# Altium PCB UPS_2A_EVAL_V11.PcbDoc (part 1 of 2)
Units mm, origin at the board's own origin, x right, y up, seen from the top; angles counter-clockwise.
Board outline 85 x 55 mm, 4 copper layers (Top Layer, Mid1, Mid2, Bottom Layer), stack 1.572 mm thick; 131 components, 65 nets, 459 pads, 411 vias.
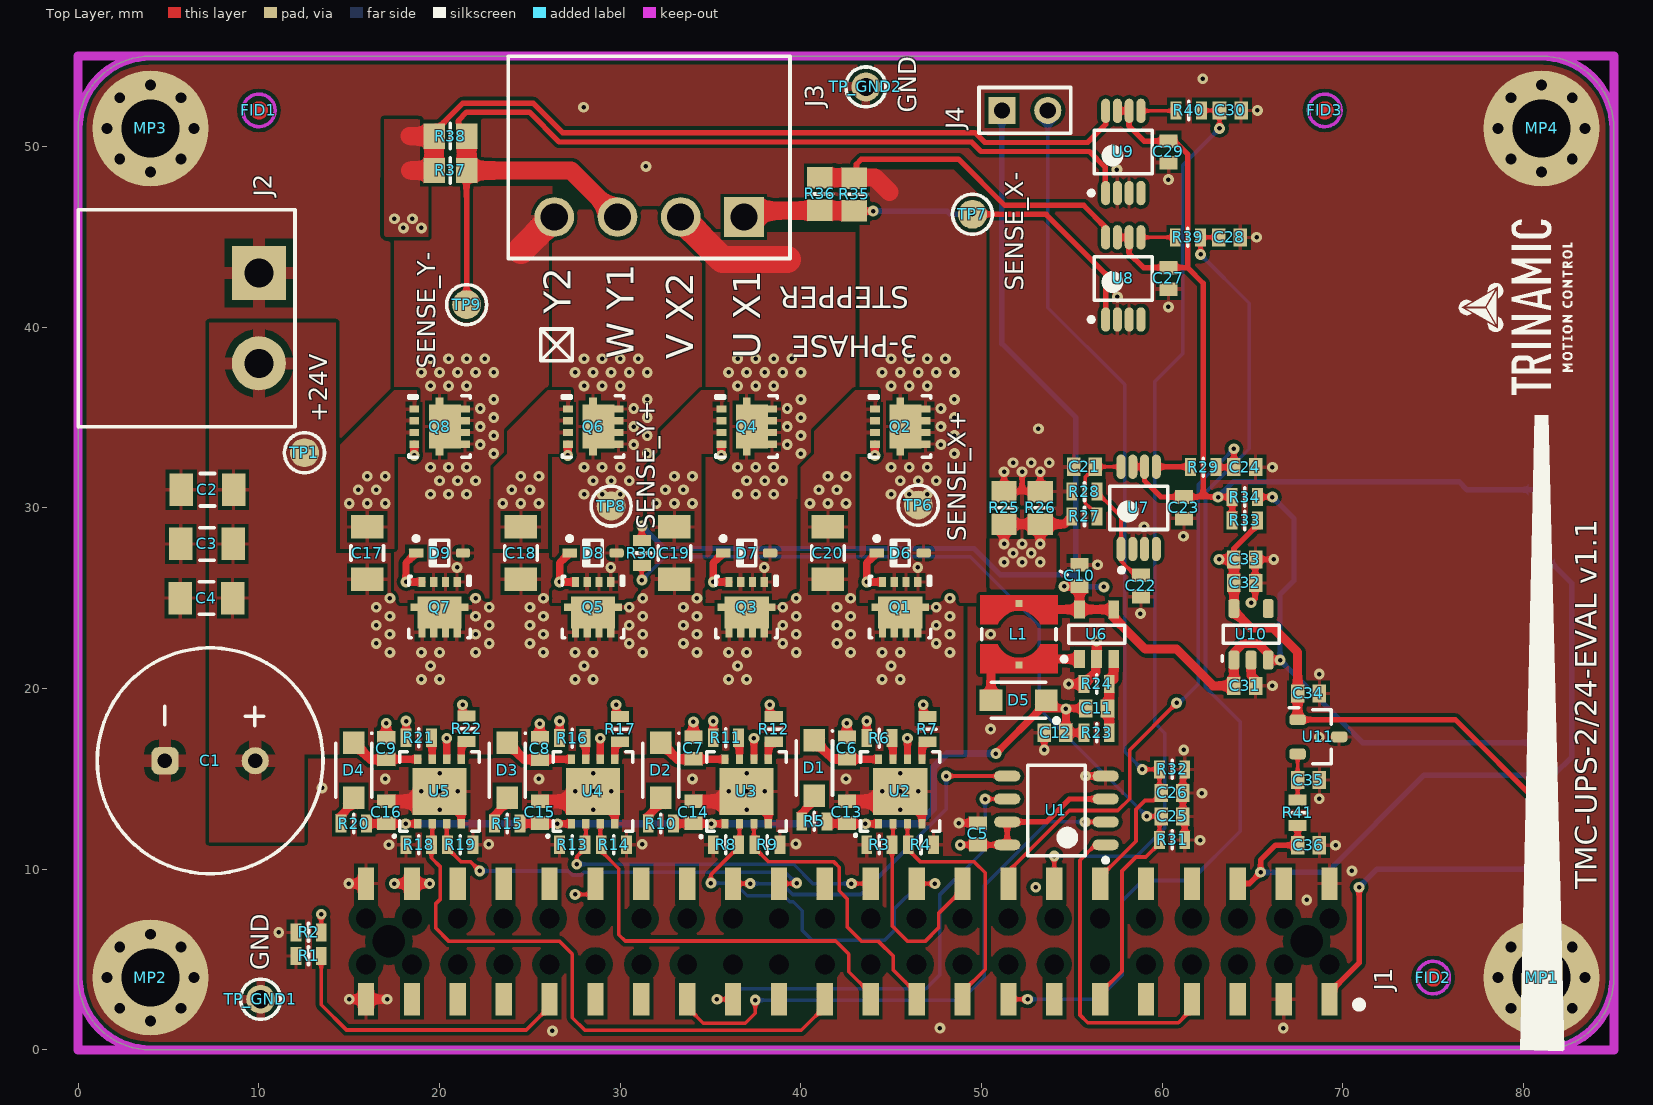
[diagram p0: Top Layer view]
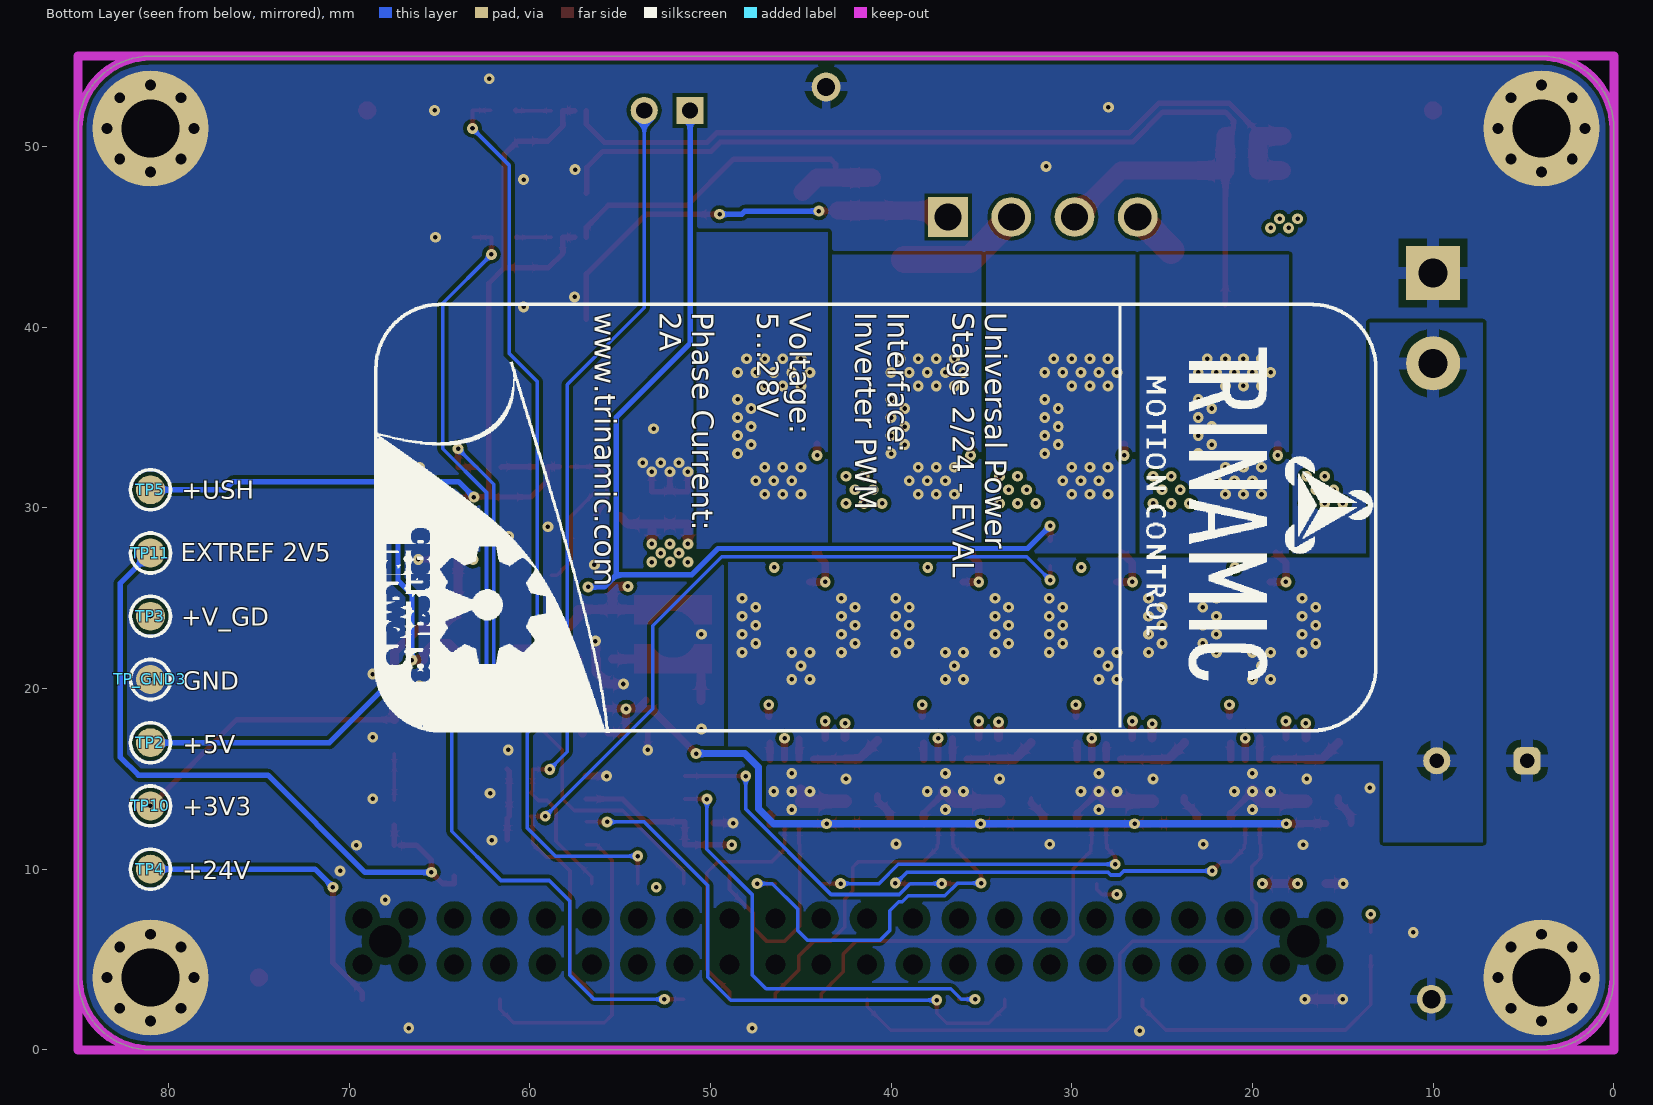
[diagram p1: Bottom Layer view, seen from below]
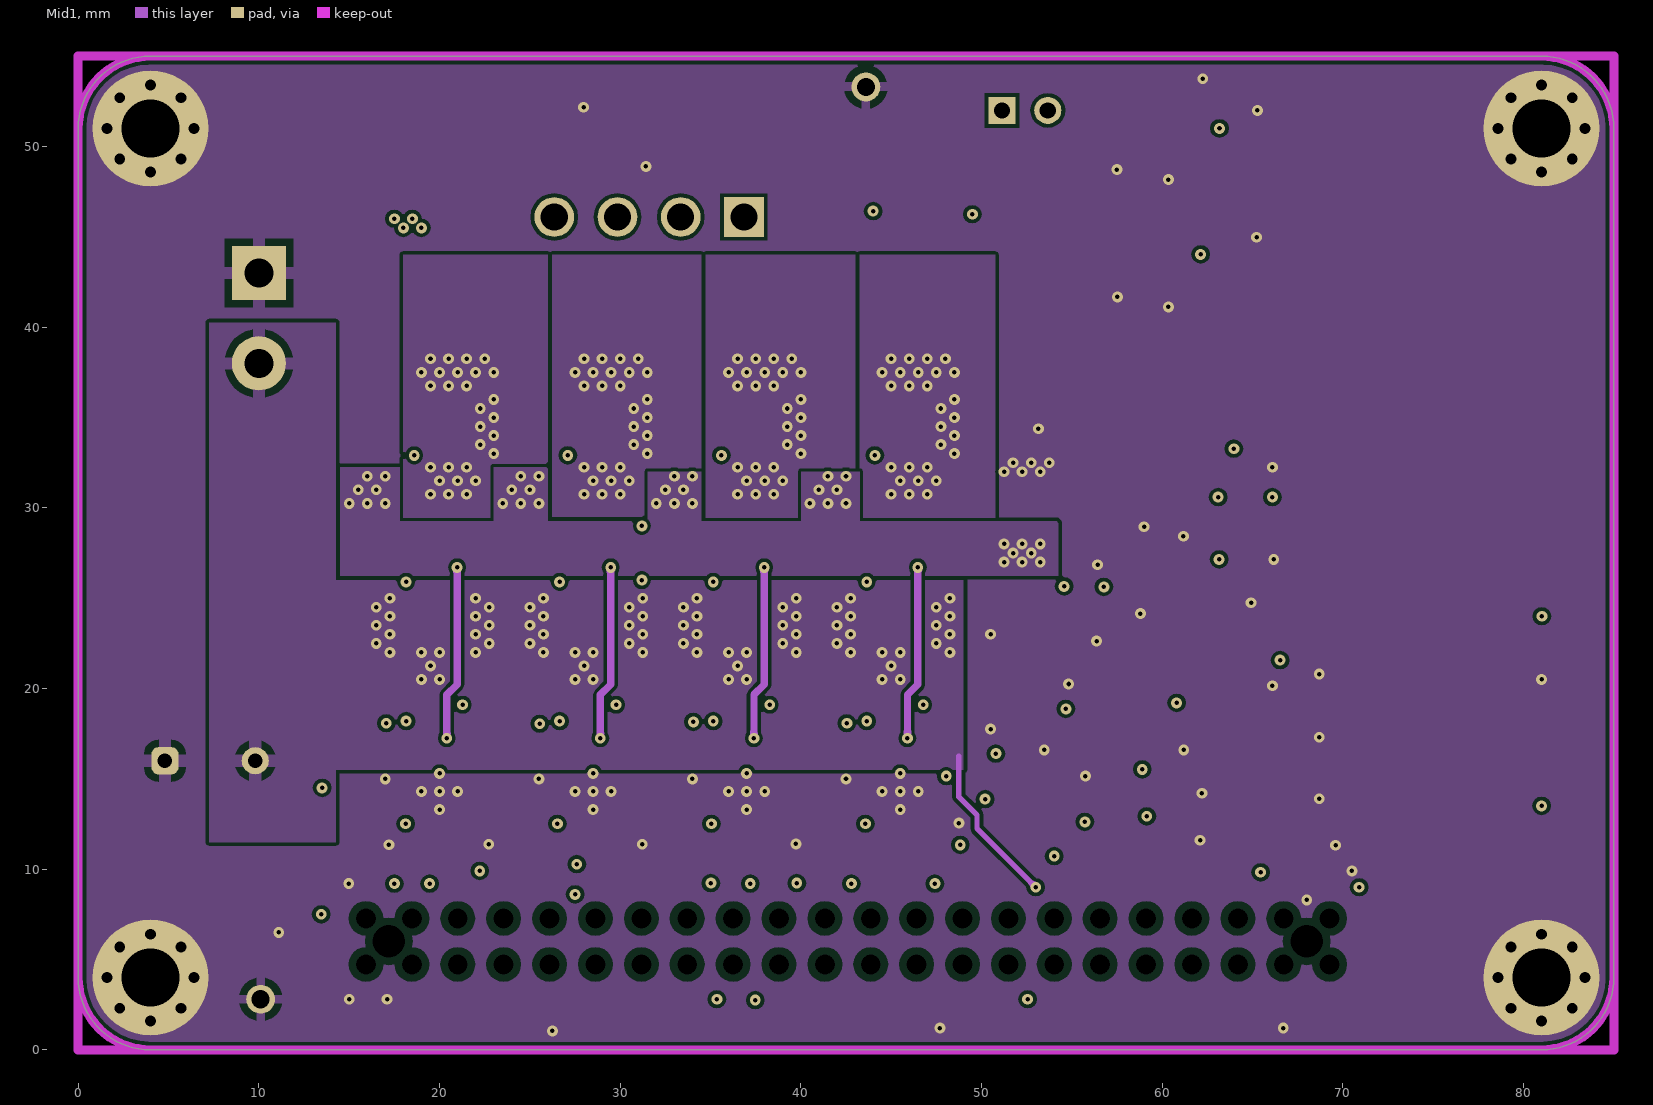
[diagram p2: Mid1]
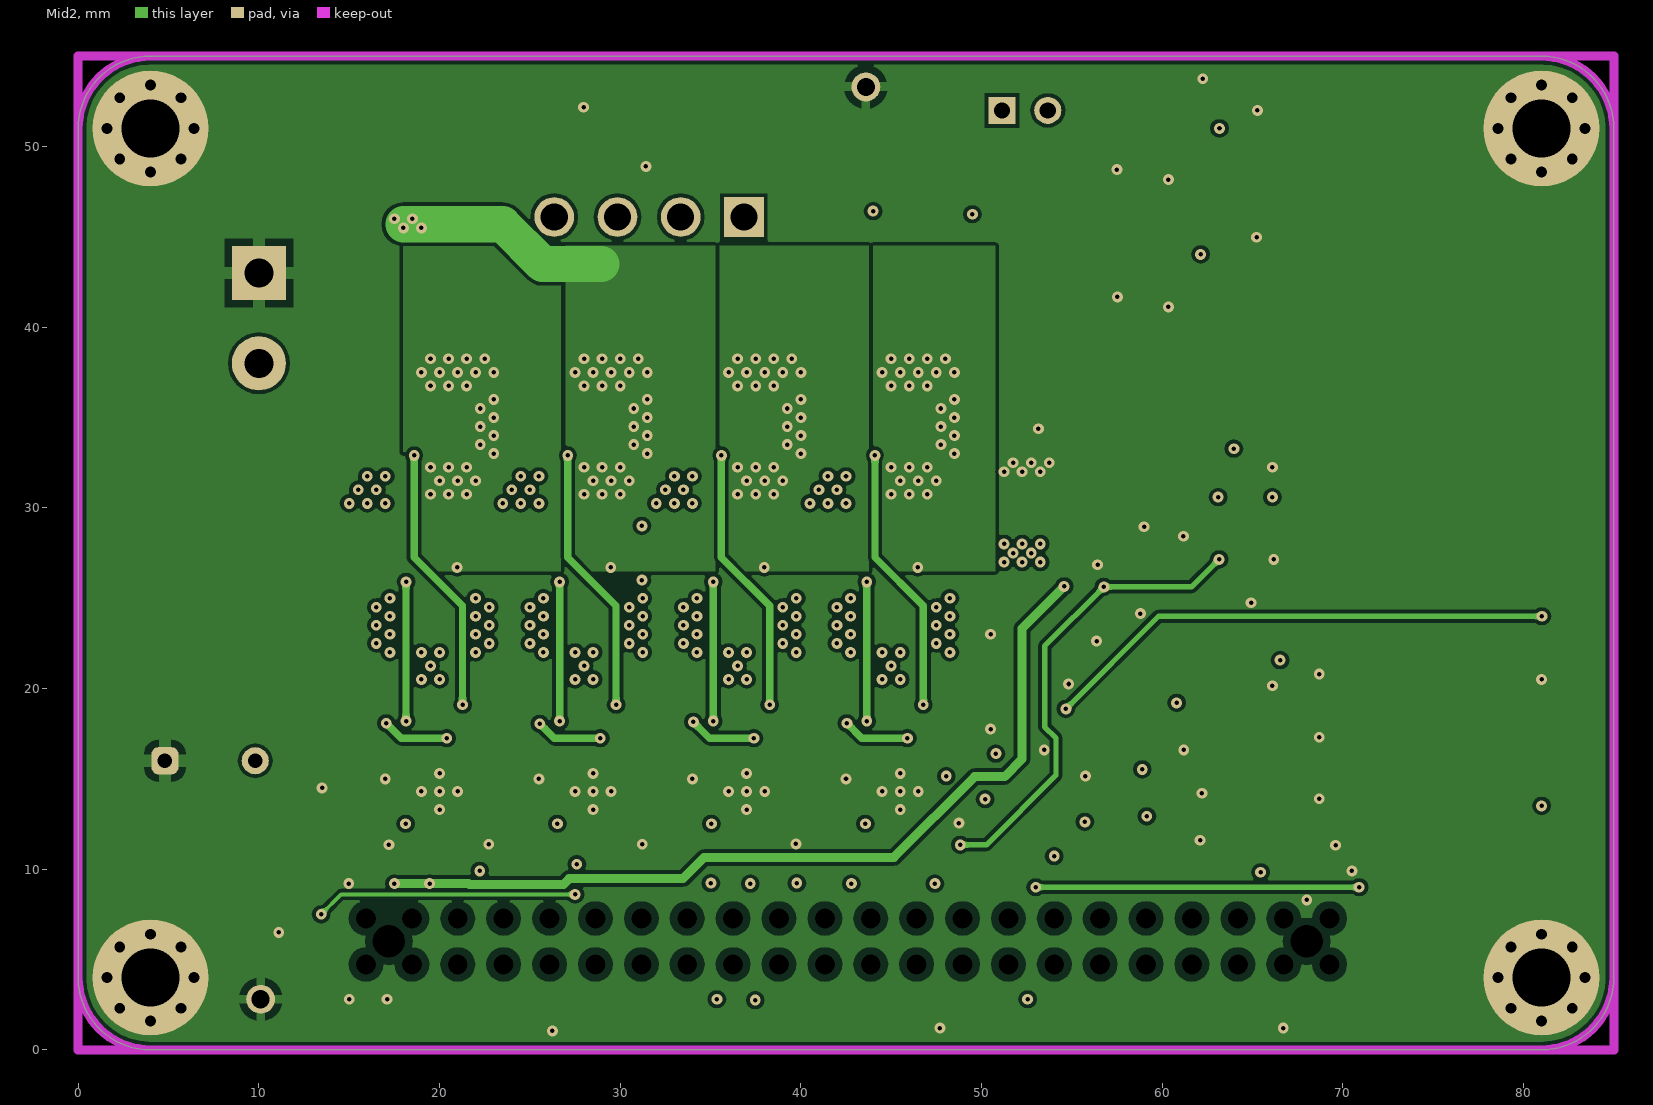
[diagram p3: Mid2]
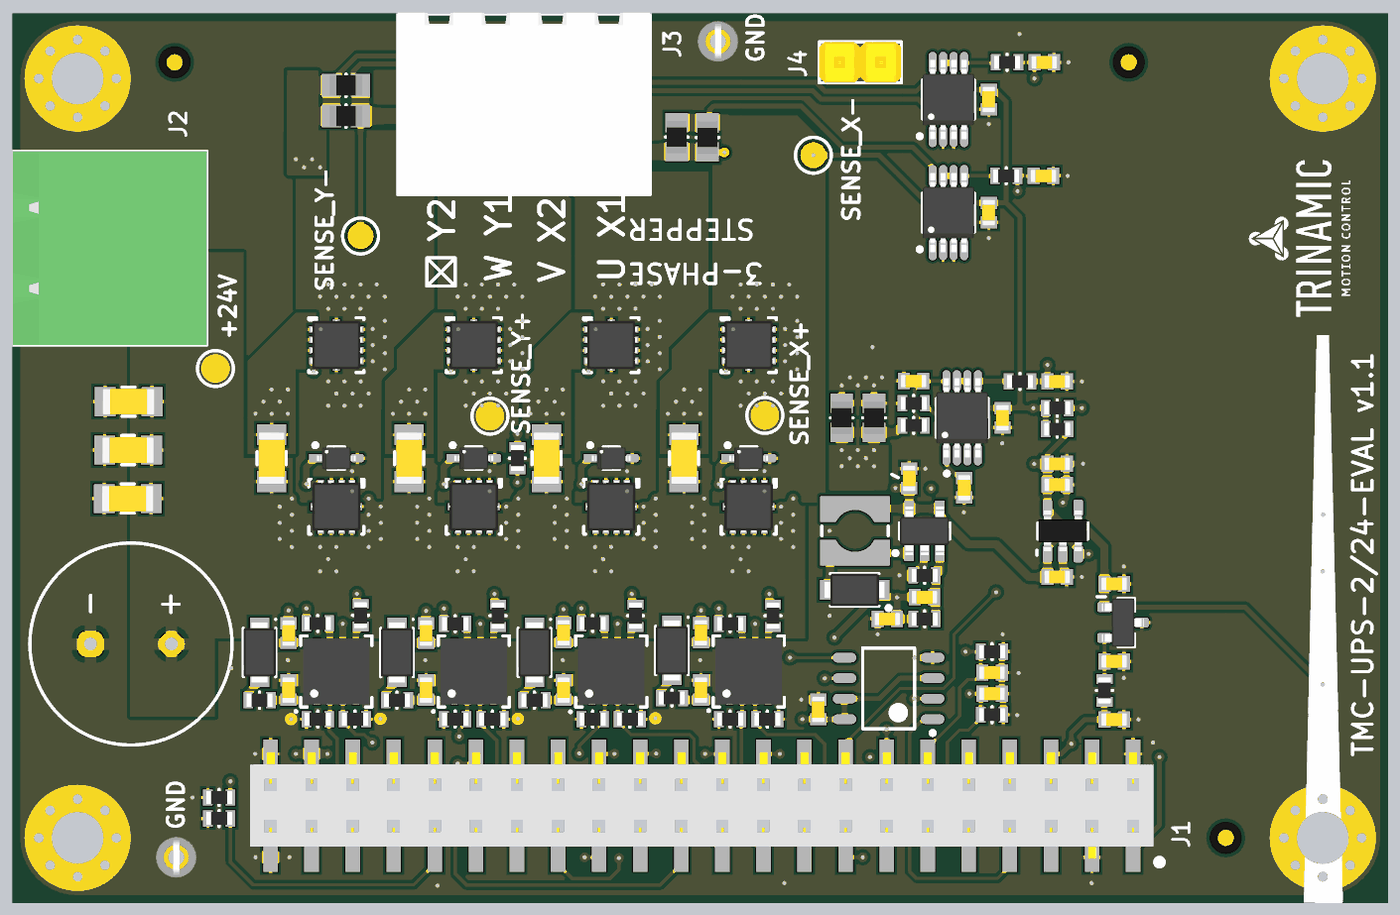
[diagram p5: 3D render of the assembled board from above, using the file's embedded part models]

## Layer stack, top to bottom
Top Soldermask: solder mask 0.0102, Solder Resist, Dk 3.5
Top Layer: signal copper 0.035
Prepreg 7628-45: prepreg 0.36, Dk 4.6
Mid1: signal copper 0.036
High Tg 1,08mm 35??m/35??m: core 0.71, FR-4, Dk 4.6
Mid2: signal copper 0.036
Prepreg 7628-45: prepreg 0.36, Dk 4.6
Bottom Layer: signal copper 0.035
Bottom Soldermask: solder mask 0.0102, Solder Resist, Dk 3.5

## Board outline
4,0 cw(c4,4) 0,4 0,51 cw(c4,51) 4,55 81,55 cw(c81,51) 85,51 85,4 cw(c81,4) 81,0

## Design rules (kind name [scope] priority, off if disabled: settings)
Clearance Clearance-unplated [IsPad and not PadIsPlated vs IsElectrical] p1: gap=0.4 ignorepadtopadclearanceinfootprint=FALSE
Clearance Clearance- [All] p2: gap=0.2 ignorepadtopadclearanceinfootprint=FALSE except(0: Arc-Hole Track-Hole SMDPad-Hole THPad-Hole Via-Hole Fill-Hole Poly-Hole Region-Hole Text-Hole; 0.125: SMDPad-SMDPad; 0.15: Track-SMDPad)
ComponentClearance [All] p1: gap=0 collisioncheckmode=3 verticalgap=0 showdistances=TRUE
DiffPairsRouting [All] p1: maxlimit=0.25 minlimit=0.25 mostfreqgap=0.25 toplayer_minwidth=0.381 toplayer_maxwidth=0.381 toplayer_prefwidth=0.381 midlayer1_minwidth=0.381 midlayer1_maxwidth=0.381 midlayer1_prefwidth=0.381 midlayer2_minwidth=0.381 midlayer2_maxwidth=0.381 midlayer2_prefwidth=0.381 bottomlayer_minwidth=0.381 bottomlayer_maxwidth=0.381 bottomlayer_prefwidth=0.381 maxuncoupledlength=12.5
FabricationTestpoint [All] p1: side=3 testpointundercomponent=TRUE minsize=0.5 maxsize=2.54 preferedsize=1.524 minholesize=0 maxholesize=1.016 preferedholesize=0.813 testpointgrid=0.025 allowsidetop=TRUE allowsidebottom=TRUE usegrid=FALSE gridtolerance=0
Height [All] p1: minheight=0 maxheight=40 prefheight=12.5
HoleSize HoleSize-PTH [All] p1: absolutevalues=TRUE maxlimit=6 minlimit=0.2 maxpercent=80.000 minpercent=20.000
HoleToHoleClearance [All] p1: gap=0.15 allowstackedmicrovias=TRUE
MinimumAnnularRing "Minimum IAR  >0.45mm" [((ObjectKind = 'Pad') OR (ObjectKind = 'Via')) And (Layer = 'MultiLayer') And (HoleDiameter > AsMM(0.45))] p1: minimumring=0.15 // minimum inner annular ring for pads > 0.45mm finished hole size
MinimumAnnularRing "Minimum IAR <=0.45mm" [((ObjectKind = 'Pad') OR (ObjectKind = 'Via')) And (Layer = 'MultiLayer') And (HoleDiameter <= AsMM(0.45))] p2: minimumring=0.15 // minimum inner annular ring for pads <= 0.45mm finished hole size
MinimumSolderMaskSliver [All] p1: minsoldermaskwidth=0.1
PlaneClearance PlaneClearance-IPI [All] p1: clearance=0.4
PlaneConnect [All] p1: planeconnectstyle=Relief reliefexpansion=0.4 reliefentries=4 reliefconductorwidth=0.2 reliefairgap=0.2
PolygonConnect PolygonConnect-Shunt [HasFootprint('RESC5025X07N')] p1: connectstyle=Direct reliefconductorwidth=0.254 reliefentries=4 polygonreliefangle="90 Angle" airgapwidth=0.254
PolygonConnect PolygonConnect-MT [HasFootprint('MTG3,2_6,4-VIA')] p2: connectstyle=Direct reliefconductorwidth=0.254 reliefentries=4 polygonreliefangle="90 Angle" airgapwidth=0.254
PolygonConnect PolygonConnect-JP2 [HasFootprint('691313710002')] p3: connectstyle=Relief reliefconductorwidth=0.7 reliefentries=4 polygonreliefangle="90 Angle" airgapwidth=0.4
PolygonConnect PolygonConnect-J2 [HasFootprint('AKL320-02')] p4: connectstyle=Relief reliefconductorwidth=0.7 reliefentries=4 polygonreliefangle="90 Angle" airgapwidth=0.4
PolygonConnect PolygonConnect-CAP [HasFootprint('CAPAE12_5X20')] p5: connectstyle=Relief reliefconductorwidth=0.7 reliefentries=4 polygonreliefangle="90 Angle" airgapwidth=0.4
PolygonConnect PolygonConnect-TP [HasFootprint('TP100P254')] p6: connectstyle=Direct reliefconductorwidth=0.254 reliefentries=4 polygonreliefangle="90 Angle" airgapwidth=0.254
PolygonConnect PolygonConnect-TP_1 [HasFootprint('TP100P254-TH')] p7: connectstyle=Relief reliefconductorwidth=0.5 reliefentries=4 polygonreliefangle="90 Angle" airgapwidth=0.4
PolygonConnect PolygonConnect-MOSFET [HasFootprint('PG-TDSON-8')] p8: connectstyle=Direct reliefconductorwidth=0.254 reliefentries=4 polygonreliefangle="90 Angle" airgapwidth=0.254
PolygonConnect PolygonConnect-CAPC3225N [HasFootprint('CAPC3225N')] p9: connectstyle=Direct reliefconductorwidth=0.254 reliefentries=4 polygonreliefangle="90 Angle" airgapwidth=0.254
PolygonConnect PolygonConnect-Via [IsVia] p10: connectstyle=Direct reliefconductorwidth=0.2 reliefentries=4 polygonreliefangle="90 Angle" airgapwidth=0.254
PolygonConnect PolygonConnect-xTW [All] p11: connectstyle=Relief reliefconductorwidth=0.2 reliefentries=4 polygonreliefangle="90 Angle" airgapwidth=0.2
RoutingCorners [All] p1: cornerstyle=45-Degree minsetback=2.5 maxsetback=2.5
RoutingVias "RoutingVias <= 0.45mm" [All] p1: holewidth=0.25 width=0.6 viastyle="Through Hole" minholewidth=0.2 minwidth=0.5 maxholewidth=0.6 maxwidth=1
SilkToSilkClearance [All] p1: silktosilkclearance=0.2
SilkToSolderMaskClearance SilkscreenOverComponentPads [IsPad] p1: minsilkscreentomaskgap=0.2 clearancetoexposedcopper=TRUE
SolderMaskExpansion SolderMaskExpansionVia [IsVia] p1: expansion=0.1 soldermaskfromhole=TRUE
SolderMaskExpansion [All] p2: expansion=0.08
Width Width-xTW [All] p1: maxlimit=2 minlimit=0.15 preferedwidth=0.2 midlayer1_minwidth=0.2 midlayer2_minwidth=0.2 bottomlayer_minwidth=0.2 minimp=50.000000 maximp=50.000000 favimp=50.000000
18 further rules are at their usual default settings.

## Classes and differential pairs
component class UPS_2A_EVAL_V11_Main: C1 C2 C3 C4 C5 J1 J2 J3 MP1 MP2 MP3 MP4 R1 R2 TP1 TP_GND1 TP_GND2 TP_GND3 U1
component class UPS_2A_EVAL_V11_Predriver: C6 C7 C8 C9 C10 C11 C12 C13 C14 C15 C16 D1 D2 D3 D4 D5 L1 R3 R4 R5 R6 R7 R8 R9 R10 R11 R12 R13 R14 R15 R16 R17 R18 R19 R20 R21 R22 R23 R24 TP2 TP3 U2 U3 U4 U5 U6
component class UPS_2A_EVAL_V11_MOSFETs: C17 C18 C19 C20 C21 C22 C23 C24 C25 C26 D6 D7 D8 D9 J4 Q1 Q2 Q3 Q4 Q5 Q6 Q7 Q8 R25 R26 R27 R28 R29 R30 R31 R32 R33 R34 TP4 TP5 U7
component class UPS_2A_EVAL_V11_Power_Sense: C27 C28 C29 C30 C31 C32 C33 C34 C35 C36 R35 R36 R37 R38 R39 R40 R41 TP6 TP7 TP8 TP9 TP10 TP11 U8 U9 U10 U11

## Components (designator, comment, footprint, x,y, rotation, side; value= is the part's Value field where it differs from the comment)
C1 "CAPP2" CAPAE12_5X20 7.3,16 r0 top locked
C2 "CAPC" CAPC3216N 7.15,31 r0 top value=10u
C3 "CAPC" CAPC3216N 7.125,28 r0 top value=10u
C4 "CAPC" CAPC3216N 7.1,25 r0 top value=10u
C5 "CAPC" CAPC1608N 49.8,11.95 r270 top value=100n
C6 "CAPC" CAPC1608N 42.55,16.7 r90 top value=100n
C7 "CAPC" CAPC1608N 34.05,16.7 r90 top value=100n
C8 "CAPC" CAPC1608N 25.55,16.675 r90 top value=100n
C9 "CAPC" CAPC1608N 17.05,16.675 r90 top value=100n
C10 "CAPC" CAPC1608N 55.425,26.25 r270 top value=10u
C11 "CAPC" CAPC1608N 56.375,18.9 r180 top value=25p
C12 "CAPC" CAPC1608N 54.075,17.55 r0 top value=4.7u
C13 "CAPC" CAPC1608N 42.55,13.15 r270 top value=1u
C14 "CAPC" CAPC1608N 34.05,13.15 r270 top value=1u
C15 "CAPC" CAPC1608N 25.55,13.15 r270 top value=1u
C16 "CAPC" CAPC1608N 17.05,13.15 r270 top value=1u
C17 "CAPC" CAPC3216N 16,27.5 r270 top value=4.7u
C18 "CAPC" CAPC3216N 24.5,27.5 r270 top value=4.7u
C19 "CAPC" CAPC3216N 33,27.5 r270 top value=4.7u
C20 "CAPC" CAPC3216N 41.5,27.5 r270 top value=4.7u
C21 "CAPC" CAPC1608N 55.7,32.275 r0 top value=100p
C22 "CAPC" CAPC1608N 58.825,25.675 r90 top value=100p
C23 "CAPC" CAPC1608N 61.2,30 r90 top value=100n
C24 "" CAPC1608N 64.575,32.25 r180 top value=2.2n
C25 "CAPC" CAPC1608N 60.55,12.925 r180 top value=100n
C26 "CAPC" CAPC1608N 60.55,14.225 r180 top value=100n
C27 "CAPC" CAPC1608N 60.35,42.7 r270 top value=100n
C28 "" CAPC1608N 63.725,44.975 r180 top value=2.2n
C29 "CAPC" CAPC1608N 60.35,49.7 r90 top value=100n
C30 "" CAPC1608N 63.775,52 r180 top value=2.2n
C31 "CAPC" CAPC1608N 64.575,20.15 r180 top value=100n
C32 "CAPC" CAPC1608N 64.575,25.85 r180 top value=4.7u
C33 "CAPC" CAPC1608N 64.575,27.15 r180 top value=100n
C34 "CAPC" CAPC1608N 68.1,19.725 r180 top value=100n
C35 "CAPC" CAPC1608N 68.1,14.925 r180 top value=100n
C36 "CAPC" CAPC1608N 68.1,11.325 r180 top value=100n
D1 "DIO-SCHOTTKY" SODFL370X140-2N 40.75,15.6 r270 top value="1A, 50V"
D2 "DIO-SCHOTTKY" SODFL370X140-2N 32.25,15.475 r270 top value="1A, 50V"
D3 "DIO-SCHOTTKY" SODFL370X140-2N 23.75,15.475 r270 top value="1A, 50V"
D4 "DIO-SCHOTTKY" SODFL370X140-2N 15.25,15.475 r270 top value="1A, 50V"
D5 "DIO-SCHOTTKY" SODFL370X140-2N 52.05,19.35 r180 top value="1A, 50V"
D6 "ZENER" SOD2512X100N 45.5,27.5 r0 top value="13V, 0.3W"
D7 "ZENER" SOD2512X100N 37,27.5 r0 top value="13V, 0.3W"
D8 "ZENER" SOD2512X100N 28.5,27.5 r0 top value="13V, 0.3W"
D9 "ZENER" SOD2512X100N 20,27.5 r0 top value="13V, 0.3W"
FID1 "Comment" FID10X20 10,52 r90 top
FID2 "Comment" FID10X20 75,4 r90 top
FID3 "Comment" FID10X20 69,52 r90 top
J1 "PTC" HLE-122-02-F-DV 42.6,6 r180 top locked value=44pin
J2 "HDR1x2A" AKL320-02 10,40.5 r90 top locked value="2 pin"
J3 "HDR1x4A" PT11304HBBN 31.6,46.1 r0 top locked value="4 pin, 3.5mm"
J4 "HDR1x2" HDRP1X2_2_54 52.4,52 r0 top locked value="2 pin"
L1 "INDM" 744031100 52.075,23 r270 top value=10u
MP1 "MTG" MTG3,2_6,4-VIA 81,4 r90 top value="3.2x6.4 VIA"
MP2 "MTG" MTG3,2_6,4-VIA 4,4 r90 top value="3.2x6.4 VIA"
MP3 "MTG" MTG3,2_6,4-VIA 4,51 r90 top value="3.2x6.4 VIA"
MP4 "MTG" MTG3,2_6,4-VIA 81,51 r90 top value="3.2x6.4 VIA"
Q1 "MOSFET-ENH-N-8A" DFN65P300X90_HS-9N 45.5,24.5 r270 top value="60V 40A"
Q2 "MOSFET-ENH-N-8A" DFN65P300X90_HS-9N 45.5,34.5 r0 top value="60V 40A"
Q3 "MOSFET-ENH-N-8A" DFN65P300X90_HS-9N 37,24.5 r270 top value="60V 40A"
Q4 "MOSFET-ENH-N-8A" DFN65P300X90_HS-9N 37,34.5 r0 top value="60V 40A"
Q5 "MOSFET-ENH-N-8A" DFN65P300X90_HS-9N 28.5,24.5 r270 top value="60V 40A"
Q6 "MOSFET-ENH-N-8A" DFN65P300X90_HS-9N 28.5,34.5 r0 top value="60V 40A"
Q7 "MOSFET-ENH-N-8A" DFN65P300X90_HS-9N 20,24.5 r270 top value="60V 40A"
Q8 "MOSFET-ENH-N-8A" DFN65P300X90_HS-9N 20,34.5 r0 top value="60V 40A"
R1 "RESC" RESC1608N 12.75,5.2 r0 top value=10k
R2 "RESC" RESC1608N 12.75,6.5 r0 top value=10k
R3 "RESC" RESC1608N 44.35,11.35 r0 top value=10k
R4 "RESC" RESC1608N 46.65,11.35 r180 top value=10k
R5 "" RESC1608N 40.75,12.65 r180 top value=2.2
R6 "" RESC1608N 44.35,17.25 r180 top value=2.2
R7 "" RESC1608N 47,17.75 r90 top value=2.2
R8 "RESC" RESC1608N 35.85,11.35 r0 top value=10k
R9 "RESC" RESC1608N 38.15,11.35 r180 top value=10k
R10 "" RESC1608N 32.25,12.525 r180 top value=2.2
R11 "" RESC1608N 35.85,17.275 r180 top value=2.2
R12 "" RESC1608N 38.5,17.75 r90 top value=2.2
R13 "RESC" RESC1608N 27.35,11.35 r0 top value=10k
R14 "RESC" RESC1608N 29.65,11.35 r180 top value=10k
R15 "" RESC1608N 23.75,12.525 r180 top value=2.2
R16 "" RESC1608N 27.35,17.25 r180 top value=2.2
R17 "" RESC1608N 30,17.75 r90 top value=2.2
R18 "RESC" RESC1608N 18.85,11.35 r0 top value=10k
R19 "RESC" RESC1608N 21.15,11.35 r180 top value=10k
R20 "" RESC1608N 15.25,12.525 r180 top value=2.2
R21 "" RESC1608N 18.85,17.275 r180 top value=2.2
R22 "" RESC1608N 21.5,17.775 r90 top value=2.2
R23 "RESC" RESC1608N 56.375,17.55 r180 top value=12k
R24 "RESC" RESC1608N 56.375,20.25 r0 top value=1.5k
R25 "RESC" RESC2012N 51.25,30 r270 top value=0.05
R26 "RESC" RESC2012N 53.25,30 r270 top value=0.05
R27 "RESC" RESC1608N 55.7,29.525 r0 top value=100
R28 "RESC" RESC1608N 55.7,30.9 r0 top value=100
R29 "RESC" RESC1608N 62.275,32.25 r0 top value=1k
R30 "RESC" RESC1608N 31.2,27.5 r90 top value="10k NTC"
R31 "RESC" RESC1608N 60.55,11.625 r180 top value=10k
R32 "RESC" RESC1608N 60.55,15.525 r180 top value=10k
R33 "RESC" RESC1608N 64.575,29.3 r180 top value=0
R34 "RESC" RESC1608N 64.575,30.6 r180 top value=DNP
R35 "RESC" RESC2012N 42.95,47.35 r270 top value=0.05
R36 "RESC" RESC2012N 41.05,47.375 r270 top value=0.05
R37 "RESC" RESC2012N 20.6,48.675 r0 top value=0.05
R38 "RESC" RESC2012N 20.6,50.575 r0 top value=0.05
R39 "RESC" RESC1608N 61.425,44.975 r0 top value=1k
R40 "RESC" RESC1608N 61.475,52 r0 top value=1k
R41 "RESC" RESC1608N 67.5,13.125 r270 top value=10
TP1 "+24V" TP100P254 12.525,33.05 r0 top value="c160 (P100 probe)"
TP2 "+5V" TP100P254 81,17 r180 bottom value="c160 (P100 probe)"
TP3 "+V_GD" TP100P254 81,24 r180 bottom value="c160 (P100 probe)"
TP4 "+24V" TP100P254 81,10 r180 bottom locked value="c160 (P100 probe)"
TP5 "+USH" TP100P254 81,31 r0 bottom value="c160 (P100 probe)"
TP6 "SENSE_X+" TP100P254 46.5,30.15 r90 top locked value="c160 (P100 probe)"
TP7 "SENSE_X-" TP100P254 49.5,46.25 r90 top locked value="c160 (P100 probe)"
TP8 "SENSE_Y+" TP100P254 29.5,30.1 r90 top locked value="c160 (P100 probe)"
TP9 "SENSE_Y-" TP100P254 21.5,41.25 r90 top value="c160 (P100 probe)"
TP10 "+3V3" TP100P254 81,13.5 r180 bottom locked value="c160 (P100 probe)"
TP11 "EXTREF 2V5" TP100P254 81,27.5 r180 bottom locked value="c160 (P100 probe)"
TP_GND1 "GND" TP100P254-TH 10.1,2.8 r180 top locked value="c160h100 (P100 TH)"
TP_GND2 "GND" TP100P254-TH 43.6,53.3 r180 top locked value="c160h100 (P100 TH)"
TP_GND3 "GND" TP100P254 81,20.5 r180 bottom value="c160 (P100 probe)"
U1 "" SOIC127P600X175-8N 54.15,13.25 r180 top value=128Kb
U2 "" PSON80P400X80_HS-9N 45.5,14.3 r90 top value="108V 1A"
U3 "" PSON80P400X80_HS-9N 37,14.3 r90 top value="108V 1A"
U4 "" PSON80P400X80_HS-9N 28.5,14.3 r90 top value="108V 1A"
U5 "" PSON80P400X80_HS-9N 20,14.3 r90 top value="108V 1A"
U6 "LMR62014" SOT95P280X145-5N 56.375,23 r90 top value=1.4A
U7 "*" TSOP65P490X95-8N 58.7,30 r90 top value=CMVR{}70V
U8 "*" TSOP65P490X95-8N 57.85,42.7 r90 top value=CMVR{}70V
U9 "*" TSOP65P490X95-8N 57.85,49.7 r90 top value=CMVR{}70V
U10 "" SOT95P270X145-5N 64.925,23 r90 top value="150mA 3.3V"
U11 "*" SOT95P280X130-3N 68.65,17.325 r0 top value=2.5V

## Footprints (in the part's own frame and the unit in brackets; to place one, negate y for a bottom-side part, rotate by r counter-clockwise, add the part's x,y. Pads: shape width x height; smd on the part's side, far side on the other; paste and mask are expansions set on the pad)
744031100 [mm] "Wuerth Precision Wire Wound Inductor, 2-Leads, Body 3.80x3.80mm, IPC Medium Density"
  rect 0.4x0.4 smd: 1(-1.7,0) 2(1.7,0)
  Top Layer region: -0.55,-2.15 -2.15,-2.15 -2.15,2.15 -0.55,2.15 -0.55,1.179 -0.549,1.179 -1.01,0.819 -1.267,0.293 -1.267,-0.293 -1.01,-0.819 -0.549,-1.179 -0.549,-1.179 -0.55,-1.182
  Top Layer region: 0.55,2.15 2.15,2.15 2.15,-2.15 0.55,-2.15 0.55,-1.179 0.549,-1.179 1.01,-0.819 1.267,-0.293 1.267,0.293 1.01,0.819 0.549,1.179 0.549,1.179 0.55,1.182
  silkscreen extent -0.3,-2.05 0.3,2.05, body extent -2.05,-2.05 2.05,2.05, height 1.8
AKL320-02 [mm] "Box header for AKL 349, 2-pin, RM 5.0"
  rect 3x3 hole 1.6: 1(2.5,0)
  round 3 hole 1.6: 2(-2.5,0)
  silkscreen extent -6,-2 6,10, body extent -6,-2 6,10, height 8.55
CAPAE12_5X20 [mm] "Aluminium Capacitor, Radial, H=20mm, D=12.5mm"
  rrect50% 1.5x1.5 hole 0.8: 1(-2.5,0)
  round 1.5 hole 0.8: 2(2.5,0)
  silkscreen extent -6.25,-6.25 6.25,6.25
CAPC1608N [mm] "Chip capacitor. C1608 (0603)."
  rect 0.75x1 smd: 1(-0.6,0) 2(0.6,0)
  body extent -0.8,-0.4 0.8,0.4, height 0.92
CAPC3216N [mm] "Chip capacitor. C3216 (1206)."
  rect 1.3x1.8 smd: 1(-1.45,0) 2(1.45,0)
  silkscreen extent -0.4,-0.9 0.4,0.9, body extent -1.6,-0.8 1.6,0.8, height 1.9
DFN65P300X90_HS-9N [mm] "DFN, 8-Leads, Body 3.00x3.00mm, Pitch 0.65mm, Thermal Pad 2.35x1.16mm, IPC Medium Density"
  rect 0.55x0.4 smd: 1(-1.4,0.975) 2(-1.4,0.325) 3(-1.4,-0.325) 4(-1.4,-0.975) 5(1.4,-0.975) 6(1.4,-0.325) 7(1.4,0.325) 8(1.4,0.975)
  rect 0.43x0.6 smd: 5(0,1.3) 5(0,-1.3)
  rect 1.76x2.45 smd paste-2: 9(0.3,0)
  silkscreen extent -1.7,-1.7 1.7,1.7, body extent -1.6,-1.55 1.6,1.55, height 0.8
FID10X20 [mm] "Fiducial"
  Top Layer circle w0.5: c0,0 r0.25
  Top Layer keep-out circle w0.2: c0,0 r0.9
HDRP1X2_2_54 [mm] "Pin Header, Single Row, 2 pos, 2.54mm"
  rect 1.5x1.5 hole 0.9: 1(-1.27,0)
  round 1.5 hole 0.9: 2(1.27,0)
  silkscreen extent -2.54,-1.27 2.54,1.27, body extent -2.54,-1.27 2.54,1.27, height 9.5
HLE-122-02-F-DV [mm] "24 Position Receptacle, Bottom Entry Connector Gold 0.100\" (2.54mm) Surface Mount"
  round 1 hole 1.1 unplated: 0(-26.67,-1.27) 0(-26.67,1.27) 0(-24.13,-1.27) 0(-24.13,1.27) 0(-21.59,-1.27) 0(-21.59,1.27) 0(-19.05,-1.27) 0(-19.05,1.27) 0(-16.51,-1.27) 0(-16.51,1.27) 0(-13.97,-1.27) 0(-13.97,1.27) 0(-11.43,-1.27) 0(-11.43,1.27) 0(-8.89,-1.27) 0(-8.89,1.27) 0(-6.35,-1.27) 0(-6.35,1.27) 0(-3.81,-1.27) 0(-3.81,1.27) 0(-1.27,1.27) 0(-1.27,-1.27) 0(1.27,1.27) 0(1.27,-1.27) 0(3.81,-1.27) 0(3.81,1.27) 0(6.35,-1.27) 0(6.35,1.27) 0(8.89,-1.27) 0(8.89,1.27) 0(11.43,-1.27) 0(11.43,1.27) 0(13.97,-1.27) 0(13.97,1.27) 0(16.51,-1.27) 0(16.51,1.27) 0(19.05,-1.27) 0(19.05,1.27) 0(21.59,-1.27) 0(21.59,1.27) 0(24.13,-1.27) 0(24.13,1.27) 0(26.67,-1.27) 0(26.67,1.27)
  round 1 hole 1.8 unplated: 0(-25.4,0) 0(25.4,0)
  rect 0.9x1.8 smd: 1(-26.67,3.2) 2(-26.67,-3.2) 3(-24.13,3.2) 4(-24.13,-3.2) 5(-21.59,3.2) 6(-21.59,-3.2) 7(-19.05,3.2) 8(-19.05,-3.2) 9(-16.51,3.2) 10(-16.51,-3.2) 11(-13.97,3.2) 12(-13.97,-3.2) 13(-11.43,3.2) 14(-11.43,-3.2) 15(-8.89,3.2) 16(-8.89,-3.2) 17(-6.35,3.2) 18(-6.35,-3.2) 19(-3.81,3.2) 20(-3.81,-3.2) 21(-1.27,3.2) 22(-1.27,-3.2) 23(1.27,3.2) 24(1.27,-3.2) 25(3.81,3.2) 26(3.81,-3.2) 27(6.35,3.2) 28(6.35,-3.2) 29(8.89,3.2) 30(8.89,-3.2) 31(11.43,3.2) 32(11.43,-3.2) 33(13.97,3.2) 34(13.97,-3.2) 35(16.51,3.2) 36(16.51,-3.2) 37(19.05,3.2) 38(19.05,-3.2) 39(21.59,3.2) 40(21.59,-3.2) 41(24.13,3.2) 42(24.13,-3.2) 43(26.67,3.2) 44(26.67,-3.2)
  silkscreen extent -28.5,3.3 -28.1,3.7, body extent -27.94,-3.29 27.94,3.29, height 3.51
MTG3,2_6,4-VIA [mm] "3,2mm ID/6.4mm OD mounting hole, reinforced with vias"
  round 6.4 hole 3.2 paste-3.3: 1(0,0)
PSON80P400X80_HS-9N [mm] "PSON, 8-Leads, Body 4.00x4.00mm, Pitch 0.80mm, Thermal Pad 3.00x2.60mm, IPC Medium Density"
  rect 0.55x0.4 smd: 1(-1.785,1.2) 2(-1.785,0.4) 3(-1.785,-0.4) 4(-1.785,-1.2) 5(1.785,-1.2) 6(1.785,-0.4) 7(1.785,0.4) 8(1.785,1.2)
  rect 2.6x3 smd paste-1.3: 9(0,0)
  silkscreen extent -2.47,-2.2 2.2,2.52, body extent -2.05,-2.05 2.05,2.05, height 0.8
PT11304HBBN [mm] "3.50 mm centerline, PT113xxHBBN Typ 182, pin header"
  rect 2.2x2.2 hole 1.5: 1(5.25,0)
  round 2.2 hole 1.5: 2(1.75,0) 3(-1.75,0) 4(-5.25,0)
  silkscreen extent -7.8,-2.3 7.8,8.9, body extent -7.8,-2.2 7.8,9, height 8.7
RESC1608N [mm] "Chip resistor C1608 (0603)."
  rect 0.6x1 smd: 1(-0.7,0) 2(0.7,0)
  silkscreen extent 0,-0.5 0,0.5, body extent -0.8,-0.4 0.8,0.4, height 0.45
RESC2012N [mm] "Chip resistor C2012 (0805)."
  rect 1.2x1.4 smd: 1(-0.9,0) 2(0.9,0)
  silkscreen extent 0,-0.7 0,0.7, body extent -1,-0.63 1,0.62, height 0.58
SOD2512X100N [mm] "SOD323 (SC-76), 2-Leads, Body 1.25x1.70mm, IPC Medium Density"
  rect 0.8x0.5 smd: 1(-1.3,0)
  rrect50% 0.8x0.5 smd: 2(1.3,0)
  silkscreen extent -1.42,-0.7 0.5,0.92, body extent -1.24,-0.7 1.24,0.7, height 1.1
SODFL370X140-2N [mm] "SODFL, 2-Leads, Body 1.80x3.70mm, IPC Medium Density"
  rect 1.25x1.2 smd: 1(-1.525,0) 2(1.525,0)
  silkscreen extent -2.1,-1 1.5,1.05, body extent -1.85,-1 1.85,1, height 1.4
SOIC127P600X175-8N [mm] "SOIC, 8-Leads, Body 4.90x3.90mm, Pitch 1.27mm, IPC Medium Density"
  oval 1.45x0.6 smd: 1(-2.725,1.905) 2(-2.725,0.635) 3(-2.725,-0.635) 4(-2.725,-1.905) 5(2.725,-1.905) 6(2.725,-0.635) 7(2.725,0.635) 8(2.725,1.905)
  silkscreen extent -2.85,-2.5 1.6,2.88, body extent -2,-2.5 2,2.5, height 1.75
SOT95P270X145-5N [mm] "SOT23, 5-Leads, Body 2.90x2.70mm, Pitch 0.95mm, IPC Medium Density"
  rrect50% 1.05x0.6 smd: 1(-1.425,0.95) 2(-1.425,0) 3(-1.425,-0.95) 4(1.425,-0.95) 5(1.425,0.95)
  silkscreen extent -1.5,-1.55 0.5,1.6, body extent -1.25,-1.5 1.25,1.5, height 1.1
SOT95P280X130-3N [mm] "SOT23, 3-Leads, Body 2.95x2.80mm, Pitch 0.95mm, IPC Medium Density"
  rrect50% 0.9x0.6 smd: 1(-1.15,0.95) 2(-1.15,-0.95) 3(1.15,0)
  silkscreen extent -1.6,-1.5 0.7,1.6, body extent -1.3,-1.5 1.3,1.5, height 1.1
SOT95P280X145-5N [mm] "SOT23, 5-Leads, Body 2.90x2.80mm, Pitch 0.95mm, IPC Medium Density"
  rect 1x0.6 smd: 1(-1.375,0.95) 2(-1.375,0) 3(-1.375,-0.95) 4(1.375,-0.95) 5(1.375,0.95)
  silkscreen extent -1.5,-1.55 0.5,1.92, body extent -1.5,-1.53 1.5,1.53, height 1.45
TP100P254 [mm] "1mm testpoint for 2.54mm pitch"
  round 1.6 smd paste-1: 1(0,0)
  silkscreen extent -1.11,-1.11 1.11,1.11
TP100P254-TH [mm] "1mm TH loop test-point for 2.54+ mm pitch"
  round 1.6 hole 1 paste-1: 1(0,0)
  silkscreen extent -1.11,-1.11 1.11,1.11, body extent -1.27,-1.27 1.27,1.27, height 2.57
TSOP65P490X95-8N [mm] "TSOP, 8-Leads, Body 3.00x3.00mm, Pitch 0.65mm, IPC Medium Density"
  oval 1.35x0.5 smd: 1(-2.275,0.975) 2(-2.275,0.325) 3(-2.275,-0.325) 4(-2.275,-0.975) 5(2.275,-0.975) 6(2.275,-0.325) 7(2.275,0.325) 8(2.275,0.975)
  silkscreen extent -3.57,-1.6 1.2,1.6, body extent -2.45,-1.6 2.45,1.6, height 0.95

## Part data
C1: library part 50527, "Polarized capacitor, pin 1 neg", Manufacturer=DNP
C2 C3 C4: library part 20034, "Ceramic chip capacitor", Manufacturer=Any, Package="1206 (3216 metric) chip capacitor", Part Number="10u, 35V, X5R, 1206 (3216 metric) chip capacitor", Voltage=35V
C5 C6 C7 C8 C9 C23 C25 C26 C27 C29 C31 C33 C34 C35 C36: library part 20027, "Ceramic chip capacitor", Manufacturer=Any, Package="0603 (1608 metric) chip capacitor", Part Number="100n, 50V, X5R, 0603 (1608 metric) chip capacitor", Voltage=50V
C10: library part 20111, "Ceramic chip capacitor", Manufacturer=Any, Package="0603 (1608 metric) chip capacitor", Part Number="10u, 10V, X5R, 0603 (1608 metric) chip capacitor", Voltage=10V
C11: library part 20112, "Ceramic chip capacitor", Manufacturer=Any, Package="0603 (1608 metric) chip capacitor", Part Number="25p, 50V, C0G/NP0, 0603 (1608 metric) chip capacitor", Voltage=50V
C12: library part 20113, "Ceramic chip capacitor", Manufacturer=Any, Package="0603 (1608 metric) chip capacitor", Part Number="4.7u, 25V, X5R, 0603 (1608 metric) chip capacitor", Voltage=25V
C13 C14 C15 C16: library part 20077, "Ceramic chip capacitor", Manufacturer=Any, Package="0603 (1608 metric) chip capacitor", Part Number="1u, 25V, X5R, 0603 (1608 metric) chip capacitor", Voltage=25V
C17 C18 C19 C20: library part 20078, "Ceramic chip capacitor", Manufacturer=Any, Package="1206 (3216 metric) chip capacitor", Part Number="4.7u, 50V, X5R, 1206 (3216 metric) chip capacitor", Voltage=50V
C21 C22: library part 20083, "Ceramic chip capacitor", Manufacturer=Any, Package="0603 (1608 metric) chip capacitor", Part Number="100p, 100V, C0G/NP0, 0603 (1608 metric) chip capacitor", Voltage=100V
C24 C28 C30: library part 20056, "Ceramic chip capacitor", Manufacturer=Any, Package="0603 (1608 metric) chip capacitor", Part Number="2.2n, 50V, C0G/NP0, 0603 (1608 metric) chip capacitor", Voltage=50V
C32: library part 20084, "Ceramic chip capacitor", Manufacturer=Any, Package="0603 (1608 metric) chip capacitor", Part Number="4.7u, 10V, X5R, 0603 (1608 metric) chip capacitor", Voltage=10V
D1 D2 D3 D4 D5: library part 50567, "Schottky Diode, pin1 cathode", Manufacturer="Diotec  Semiconductor", Part Number=SKL15
D6 D7 D8 D9: library part 50513, "Zener, pin1 cathode", Manufacturer=Nexperia, Part Number=BZX384-B13
J1: library part 50289, "Trinamic 44-pin connector", Manufacturer=Samtec, Part Number=HLE-122-02-F-DV
J2: library part 50537, "1X2 pin connector", Manufacturer="Metz Connect", Part Number=AKL320-02
J3: library part 50511, "1X4 pin connector", Manufacturer="Metz Connect", Part Number=PT11304HBBN
J4: library part 50023, "1X2 pin connector", Manufacturer=Any, Part Number="1x2 2.54mm pin header"
L1: library part 60031, "Molded inductor", Current=740m, Manufacturer=Wuerth, Part Number=744031100, Tolerance=30
MP1 MP2 MP3 MP4: library part 50193, "Mounting hole", Part Number="M3 mounting hole"
Q1 Q2 Q3 Q4 Q5 Q6 Q7 Q8: library part 50524, "N-ch Enh-MOSFET; 5,6,7,8D 4G 1,2.3S", Manufacturer=Infineon, Part Number=BSZ068N06NS
R1 R2 R3 R4 R8 R9 R13 R14 R18 R19 R31 R32: library part 10028, "Chip Resistor", Manufacturer=Any, Package="0603 (1608 metric) chip resistor", Part Number="10k, 1%, 100mW, 0603 (1608 metric) chip resistor", Power=100mW, Tolerance=1%
R5 R6 R7 R10 R11 R12 R15 R16 R17 R20 R21 R22: library part 10041, "Chip Resistor", Manufacturer=Any, Package="0603 (1608 metric) chip resistor", Part Number="2.2, 1%, 100mW, 0603 (1608 metric) chip resistor", Power=100mW, Tolerance=1%
R23: library part 10078, "Chip Resistor", Manufacturer=Any, Package="0603 (1608 metric) chip resistor", Part Number="12k, 1%, 100mW, 0603 (1608 metric) chip resistor", Power=100mW, Tolerance=1%
R24: library part 10152, "Chip Resistor", Manufacturer=Any, Package="0603 (1608 metric) chip resistor", Part Number="1.5k, 1%, 100mW, 0603 (1608 metric) chip resistor", Power=100mW, Tolerance=1%
R25 R26 R35 R36 R37 R38: library part 10172, "Chip Resistor", Manufacturer=Any, Package="0805 (2012 metric) chip resistor", Part Number="0.05, 1%, 250mW, 0805 (2012 metric) chip resistor", Power=250mW, Tolerance=1%
R27 R28: library part 10016, "Chip Resistor", Manufacturer=Any, Package="0603 (1608 metric) chip resistor", Part Number="100, 1%, 100mW, 0603 (1608 metric) chip resistor", Power=100mW, Tolerance=1%
R29 R39 R40: library part 10049, "Chip Resistor", Manufacturer=Any, Package="0603 (1608 metric) chip resistor", Part Number="1k, 1%, 100mW, 0603 (1608 metric) chip resistor", Power=100mW, Tolerance=1%
R30: library part 40000, "Chip Resistor", Manufacturer=Epcos, Package="0603 (1608 metric) chip resistor", Part Number=B57330V2103J260, Power=180mW, Tolerance=5%
R33: library part 10054, "Chip Resistor", Manufacturer=Any, Package="0603 (1608 metric) chip resistor", Part Number="0, -, -, 0603 (1608 metric) chip resistor", Power=-
R34: library part 40007, "Chip Resistor", Manufacturer=DNP, Package="0603 (1608 metric) chip resistor"
R41: library part 10002, "Chip Resistor", Manufacturer=Any, Package="0603 (1608 metric) chip resistor", Part Number="10, 1%, 100mW, 0603 (1608 metric) chip resistor", Power=100mW, Tolerance=1%
TP1 TP2 TP3 TP4 TP5 TP6 TP7 TP8 TP9 TP10 TP11 TP_GND3: library part 50094, "Round testpoint"
TP_GND1 TP_GND2: library part 50149, "Round testpoint"
U1: library part 50499, "SPI Serial Flash Memory", Manufacturer=Atmel, Part Number=AT25128B-SSHL
U2 U3 U4 U5: library part 50490, "High Voltage 1A Peak Half Bridge Gate Driver", Manufacturer="Texas Instruments", Part Number=LM5109BSD/NOPB
U6: library part 50495, "LMR62014 SIMPLE SWITCHER® 20Vout, 1.4A Step-Up Voltage Regulator in SOT-23", Manufacturer="Texas Instruments", Part Number=LMR62014XMF/NOPB
U7 U8 U9: library part 50496, "Bidirectional, Zero Drift, Current Sense Amplifier", Manufacturer="Analog Devices", Part Number=AD8418ABRMZ
U10: library part 50426, "150-mA Low-noise LDO", Manufacturer="Texas Instruments", Part Number=LP2985-33DBV
U11: library part 50316, "Series voltage reference", Manufacturer="Texas Instruments", Part Number=REF3125

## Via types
v1: diameter 0.6, hole 0.25, Top Layer to Bottom Layer, tented both sides, 373 vias
v2: diameter 1, hole 0.6, Top Layer to Bottom Layer, tented both sides, 32 vias
v3: diameter 0.6, hole 0.25, Top Layer to Bottom Layer, 6 vias

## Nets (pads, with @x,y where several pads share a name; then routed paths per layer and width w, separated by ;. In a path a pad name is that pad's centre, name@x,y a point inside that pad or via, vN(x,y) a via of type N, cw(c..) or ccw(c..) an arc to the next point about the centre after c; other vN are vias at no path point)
+3V3: C5.2 C32.2 C33.2 C34.2 J4.1 R30.2 R33.1 TP10.1 U1.3 U1.7 U1.8 U10.5 U11.1 | length 121.1
  Top Layer w0.3: R30.2@31.2,28.2 v1(31.2,29) ; v1(48.825,11.345) U1.8@51.425,11.345 U1.7@51.425,12.615 53.59,12.615 54.86,13.885 U1.3@56.875,13.885 ; C33.2@63.975,27.15 63.975,27.75 65.275,29.05 R33.1@65.275,29.3 ; U11.1@67.5,18.275 76.225,18.275 v1(81,13.5)
  Top Layer w0.5: v1(63.15,27.15) C33.2@63.975,27.15 U10.5@63.975,24.425 63.975,24.275 64.9,23.35 66.15,23.35 67.5,22 67.5,20.75 C34.2@67.5,19.725 U11.1@67.5,18.275
  Mid2 w0.3: v1(48.825,11.345) 50.27,11.345 54.125,15.2 54.125,17.25 53.5,17.875 53.5,22.35 v1(56.775,25.625) 61.625,25.625 v1(63.15,27.15)
  Bottom Layer w0.3: v1@31.2,29.025 v1(31.2,29) 32.45,27.75 49.575,27.75 51.025,26.3 55.2,26.3 ; J4.1@51.13,52 51.13,39.089 55.225,34.994 55.225,26.325 55.2,26.3 ; v1(56.775,25.625) 55.875,25.625 55.2,26.3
